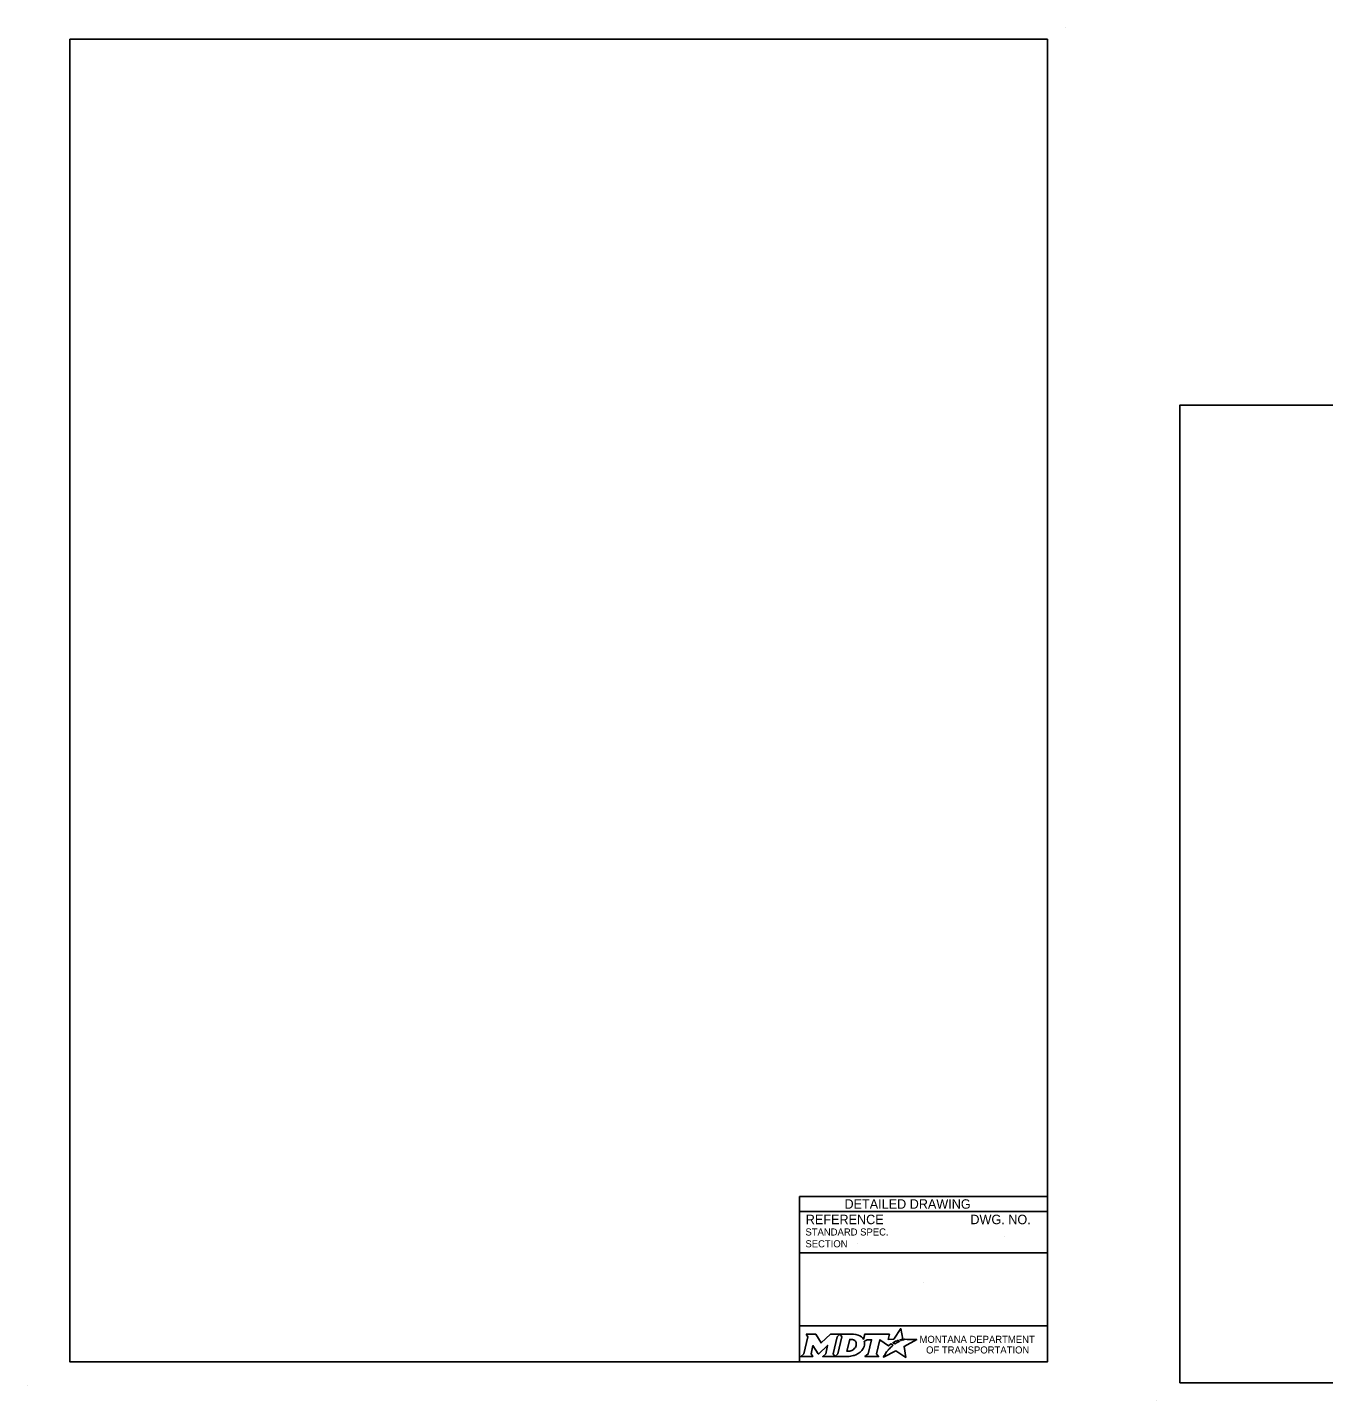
# Model space of a CAD drawing. Extents: x 49991.4 to 50021, y 49987.6 to 50011.4.
# Drawn here: x 49999.98 to 50010.95, y 49999.74 to 50011.36 of the extents above; entities that cross this region are included whole.
import ezdxf

# ---------------------------------------------------------------- set-up
doc = ezdxf.new("R2010")
doc.units = 0
doc.layers.add('Level 1', color=7, linetype='Continuous')
doc.layers.add('Level 2', color=7, linetype='Continuous')

msp = doc.modelspace()

# ---------------------------------------------------------------- linework, layer by layer
at = {"layer": 'Level 1'}
for p, q in [((50008.765, 50011.363), (50008.765, 50011.363)), ((49999.977, 49999.862), (49999.977, 49999.862)), ((50009.537, 49999.736), (50009.537, 49999.736))]:
    msp.add_line(p, q, dxfattribs=at)
for points in [[(50008.615, 50011.263), (50000.336, 50011.263), (50000.336, 50000.062), (50008.615, 50000.062)], [(50020.938, 50008.165), (50009.737, 50008.165), (50009.737, 49999.886), (50020.938, 49999.886)]]:
    msp.add_lwpolyline(points, close=True, dxfattribs=at)
at = {"layer": 'Level 2'}
for p, q in [((50008.615, 50001.462), (50006.515, 50001.462)), ((50006.515, 50001.462), (50006.515, 50000.062)), ((50008.615, 50001.337), (50006.515, 50001.337)), ((50007.009, 50001.063), (50007.009, 50001.063)), ((50008.251, 50001.122), (50008.251, 50001.122)), ((50008.615, 50000.987), (50006.515, 50000.987)), ((50007.565, 50000.738), (50007.565, 50000.738)), ((50008.615, 50000.369), (50006.515, 50000.369))]:
    msp.add_line(p, q, dxfattribs=at)
for points in [[(50007.377, 50000.245), (50007.367, 50000.25), (50007.378, 50000.253), (50007.39, 50000.255), (50007.373, 50000.345), (50007.313, 50000.254), (50007.266, 50000.253), (50007.276, 50000.297), (50007.067, 50000.297), (50007.057, 50000.255), (50007.051, 50000.263)], [(50006.57, 50000.297), (50006.584, 50000.274), (50006.551, 50000.131), (50006.525, 50000.108), (50006.627, 50000.108), (50006.613, 50000.131), (50006.629, 50000.201), (50006.673, 50000.132), (50006.678, 50000.132), (50006.753, 50000.202), (50006.737, 50000.13), (50006.712, 50000.108), (50006.814, 50000.108), (50006.8, 50000.132), (50006.833, 50000.274)], [(50006.833, 50000.274), (50006.859, 50000.297), (50006.776, 50000.297), (50006.697, 50000.224), (50006.652, 50000.297), (50006.57, 50000.297)], [(50006.972, 50000.297), (50006.859, 50000.297), (50006.873, 50000.275), (50006.839, 50000.131), (50006.814, 50000.108), (50006.925, 50000.108)], [(50006.996, 50000.211), (50006.995, 50000.203), (50006.992, 50000.193), (50006.988, 50000.185), (50006.982, 50000.178), (50006.976, 50000.171), (50006.968, 50000.164), (50006.959, 50000.16), (50006.95, 50000.156), (50006.941, 50000.154), (50006.932, 50000.153), (50006.916, 50000.153), (50006.94, 50000.253), (50006.956, 50000.253), (50006.963, 50000.252), (50006.971, 50000.25), (50006.977, 50000.247), (50006.983, 50000.243), (50006.988, 50000.238), (50006.992, 50000.232), (50006.995, 50000.226), (50006.996, 50000.218), (50006.996, 50000.215), (50006.996, 50000.211)], [(50007.064, 50000.238), (50007.088, 50000.251), (50007.125, 50000.251), (50007.097, 50000.131), (50007.069, 50000.108), (50007.185, 50000.108), (50007.168, 50000.131), (50007.196, 50000.251), (50007.268, 50000.2), (50007.289, 50000.215), (50007.309, 50000.204)], [(50007.253, 50000.148), (50007.237, 50000.124), (50007.233, 50000.116), (50007.227, 50000.107), (50007.225, 50000.103), (50007.33, 50000.156), (50007.414, 50000.101), (50007.401, 50000.194), (50007.508, 50000.252), (50007.458, 50000.253), (50007.428, 50000.253), (50007.407, 50000.254), (50007.401, 50000.252), (50007.396, 50000.251), (50007.387, 50000.249), (50007.377, 50000.245)], [(50007.327, 50000.217), (50007.324, 50000.215), (50007.306, 50000.225), (50007.316, 50000.231), (50007.32, 50000.233), (50007.329, 50000.237), (50007.335, 50000.239), (50007.343, 50000.243), (50007.35, 50000.245), (50007.362, 50000.238), (50007.358, 50000.236), (50007.353, 50000.233), (50007.349, 50000.231), (50007.344, 50000.228), (50007.342, 50000.227), (50007.339, 50000.225), (50007.337, 50000.224), (50007.334, 50000.222), (50007.332, 50000.221), (50007.329, 50000.219), (50007.327, 50000.217)], [(50006.97, 50000.116), (50006.979, 50000.118), (50006.992, 50000.124), (50007.012, 50000.135)], [(50007.267, 50000.164), (50007.267, 50000.164)]]:
    msp.add_lwpolyline(points, dxfattribs=at)
for centre, radius, start, end in [((50006.995, 50000.219), 0.0709, 339.5329, 15.8582), ((50006.951, 50000.236), 0.118, 300.9103, 339.1383)]:
    msp.add_arc(centre, radius, start, end, dxfattribs=at)
for centre, major_axis, ratio, start_param, end_param in [((50006.97, 50000.25), (0.0834, -0.0037), 0.568097, 0.61298, 1.570796), ((50007.026, 50000.257), (0.0361, -0.0295), 0.469099, 1.225588, 1.570796), ((50006.925, 50000.257), (0, 0.148), 0.987302, 3.139398, 3.456847), ((50007.26, 50000.156), (-0.00694, -0.00806), 0.008222, 0, 3.137361), ((50007.276, 50000.174), (-0.0098, -0.0102), 0.016458, 3.141593, 6.279097), ((50007.297, 50000.194), (-0.0112, -0.0097), 0.021651, 3.157348, 6.283185)]:
    msp.add_ellipse(centre, major_axis=major_axis, ratio=ratio, start_param=start_param, end_param=end_param, dxfattribs=at)

# ---------------------------------------------------------------- texts
for s, height, p in [('DETAILED DRAWING', 0.0799, (50006.896, 50001.36)), ('REFERENCE', 0.08, (50006.568, 50001.229)), ('DWG. NO.', 0.08, (50007.962, 50001.229)), ('STANDARD SPEC.', 0.06, (50006.565, 50001.133)), ('SECTION', 0.06, (50006.565, 50001.033)), ('MONTANA DEPARTMENT', 0.06, (50007.531, 50000.224)), ('OF TRANSPORTATION', 0.06, (50007.587, 50000.134))]:
    msp.add_text(s, height=height, dxfattribs=at).set_placement(p)

doc.saveas('drawing.dxf')
